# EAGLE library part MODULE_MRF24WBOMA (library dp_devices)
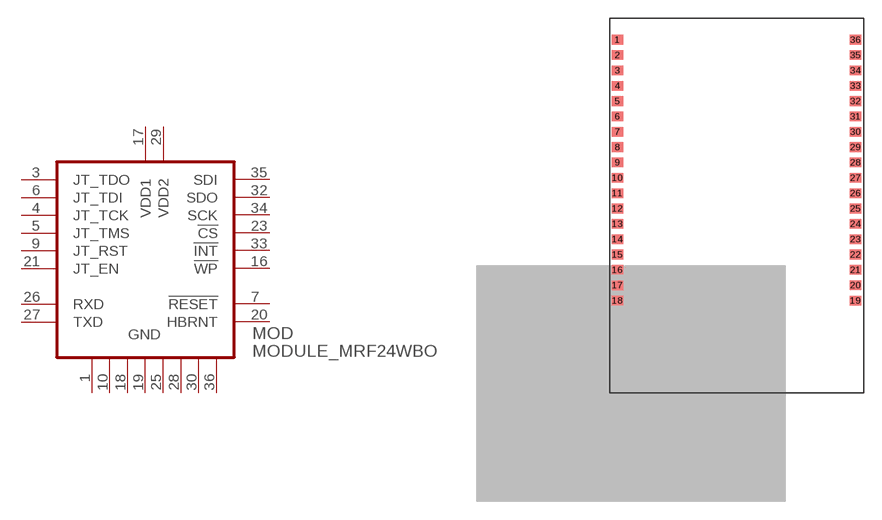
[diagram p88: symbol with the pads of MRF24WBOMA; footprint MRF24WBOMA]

Designator prefix MOD

## MODULE_MRF24WBOMA  [MRF24WBOMA]
1  GND1  pwr
3  JT_TDO
4  JT_TCK
5  JT_TMS
6  JT_TDI
7  !RESET
9  JT_RST
10  GND2  pwr
16  !WP
17  VDD1
18  GND3  pwr
19  GND4  pwr
20  HBRNT
21  JT_EN
23  !CS
25  GND5  pwr
26  RXD
27  TXD
28  GND6  pwr
29  VDD2
30  GND7  pwr
32  SDO
33  !INT
34  SCK
35  SDI
36  GND8  pwr

## Footprint MRF24WBOMA (pad centres in mm)
smd 0.95 x 0.8: 1 -9.865,13.71; 2 -9.865,12.44; 3 -9.865,11.17; 4 -9.865,9.9; 5 -9.865,8.63; 6 -9.865,7.36; 7 -9.865,6.09; 8 -9.865,4.82; 9 -9.865,3.55; 10 -9.865,2.28; 11 -9.865,1.01; 12 -9.865,-0.26; 13 -9.865,-1.53; 14 -9.865,-2.8; 15 -9.865,-4.07; 16 -9.865,-5.34; 17 -9.865,-6.61; 18 -9.865,-7.88; 19 9.82,-7.88; 20 9.82,-6.61; 21 9.82,-5.34; 22 9.82,-4.07; 23 9.82,-2.8; 24 9.82,-1.53; 25 9.82,-0.26; 26 9.82,1.01; 27 9.82,2.28; 28 9.82,3.55; 29 9.82,4.82; 30 9.82,6.09; 31 9.82,7.36; 32 9.82,8.63; 33 9.82,9.9; 34 9.82,11.17; 35 9.82,12.44; 36 9.82,13.71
